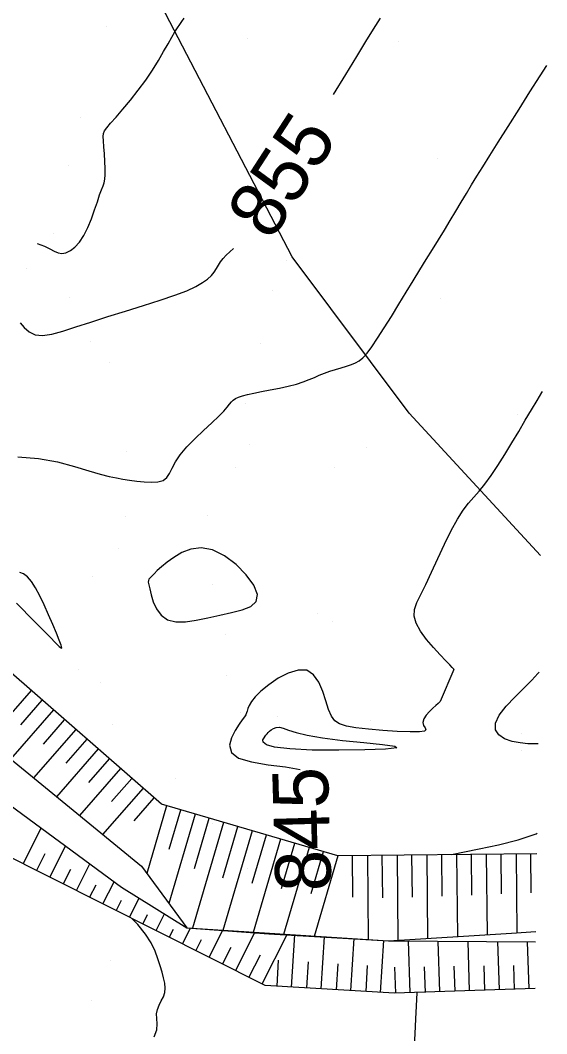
# Model space of a CAD drawing. Extents: x 400243 to 403697, y 4403637 to 4408083.
# Drawn here: x 403024.9 to 403095.7, y 4406214.4 to 4406350.8 of the extents above; entities that cross this region are included whole.
import ezdxf

# ---------------------------------------------------------------- set-up
doc = ezdxf.new("R2010")
doc.units = 0
doc.layers.add('HH_IC', color=7, linetype='Continuous')

msp = doc.modelspace()

# ---------------------------------------------------------------- linework, layer by layer
at = {"layer": 'HH_IC'}
for p, q in [((403061.46, 4406318.99), (403038.98, 4406362.21)), ((403036.51, 4406349.98), (403036.51, 4406349.98)), ((403055.41, 4406348.4), (403055.41, 4406348.4)), ((403075.73, 4406348.02), (403075.73, 4406348.02)), ((403032.92, 4406337.8), (403032.92, 4406337.8)), ((403031.33, 4406331.25), (403031.33, 4406331.25)), ((403081, 4406332.21), (403081, 4406332.21)), ((403060.68, 4406330.52), (403060.68, 4406330.52)), ((403029.3, 4406322.1), (403029.3, 4406322.1)), ((403061.46, 4406318.99), (403061.46, 4406318.99)), ((403077.2, 4406297.93), (403061.46, 4406318.99)), ((403060.74, 4406318.52), (403060.74, 4406318.52)), ((403025.73, 4406317.41), (403025.73, 4406317.41)), ((403031.47, 4406313.56), (403031.47, 4406313.56)), ((403058.75, 4406314.5), (403058.75, 4406314.5)), ((403081.37, 4406313.4), (403081.37, 4406313.4)), ((403034.38, 4406307.58), (403034.38, 4406307.58)), ((403057.14, 4406307.34), (403057.14, 4406307.34)), ((403036.88, 4406304.71), (403036.88, 4406304.71)), ((403055.11, 4406299.27), (403055.11, 4406299.27)), ((403077.2, 4406297.93), (403077.2, 4406297.93)), ((403094.88, 4406278.76), (403077.2, 4406297.93)), ((403091.72, 4406297.78), (403091.72, 4406297.78)), ((403055.73, 4406293.67), (403055.73, 4406293.67)), ((403071.52, 4406293.28), (403071.52, 4406293.28)), ((403039.17, 4406292.83), (403039.17, 4406292.83)), ((403053.79, 4406290.58), (403053.79, 4406290.58)), ((403067.09, 4406290.64), (403067.09, 4406290.64)), ((403039, 4406284.08), (403039, 4406284.08)), ((403050.03, 4406284.19), (403050.03, 4406284.19)), ((403038.04, 4406279.67), (403038.04, 4406279.67)), ((403034.58, 4406275.91), (403034.58, 4406275.91)), ((402983.55, 4406274.63), (403038.5, 4406234.11)), ((403050.69, 4406274.86), (403050.69, 4406274.86)), ((403064.8, 4406271.03), (403064.8, 4406271.03)), ((403066.88, 4406269.83), (403066.88, 4406269.83)), ((403052.55, 4406268.13), (403052.55, 4406268.13)), ((403043.88, 4406245.29), (403022.92, 4406263.59)), ((403032.76, 4406263.37), (403032.76, 4406263.37)), ((403035.68, 4406261.66), (403035.68, 4406261.66)), ((403052.57, 4406262.68), (403052.57, 4406262.68)), ((403026.32, 4406260.62), (403020.47, 4406253.91)), ((403024.92, 4406255.97), (403027.83, 4406259.3)), ((403029.33, 4406257.99), (403023.56, 4406251.38)), ((403054.53, 4406257.58), (403054.53, 4406257.58)), ((403027.97, 4406253.39), (403030.84, 4406256.67)), ((403059.46, 4406257.04), (403059.46, 4406257.04)), ((403071.95, 4406256.51), (403071.95, 4406256.51)), ((403032.35, 4406255.36), (403026.66, 4406248.84)), ((403037.32, 4406256.08), (403037.32, 4406256.08)), ((403092.37, 4406254.83), (403092.37, 4406254.83)), ((403019.57, 4406254.65), (403041.16, 4406236.95)), ((403031.03, 4406250.81), (403033.85, 4406254.04)), ((403035.36, 4406252.73), (403029.75, 4406246.3)), ((403059.55, 4406253.3), (403059.55, 4406253.3)), ((403092.3, 4406252.54), (403092.3, 4406252.54)), ((403034.08, 4406248.22), (403036.87, 4406251.41)), ((403038.37, 4406250.1), (403032.85, 4406243.76)), ((403037.14, 4406245.64), (403039.88, 4406248.78)), ((403045.72, 4406248.79), (403045.72, 4406248.79)), ((403041.39, 4406247.46), (403035.94, 4406241.23)), ((403040.19, 4406243.05), (403042.89, 4406246.15)), ((403043.88, 4406245.29), (403043.88, 4406245.29)), ((403067.61, 4406238.36), (403043.88, 4406245.29)), ((403044.54, 4406245.09), (403041.88, 4406235.97)), ((403048.38, 4406243.97), (403044.87, 4406231.93)), ((403044.92, 4406239.24), (403046.46, 4406244.53)), ((403052.22, 4406242.85), (403048.06, 4406228.59)), ((403048.33, 4406236.66), (403050.3, 4406243.41)), ((403050.69, 4406242.7), (403050.69, 4406242.7)), ((403025.27, 4406237.28), (403027.69, 4406242.08)), ((403052.12, 4406235.37), (403054.14, 4406242.29)), ((403056.06, 4406241.73), (403052.14, 4406228.3)), ((403056.08, 4406234.66), (403057.98, 4406241.17)), ((403057.81, 4406220.9), (403017.84, 4406241.02)), ((403059.9, 4406240.61), (403056.22, 4406228.01)), ((403060.04, 4406233.96), (403061.82, 4406240.05)), ((403088.41, 4406240.11), (403088.41, 4406240.11)), ((403028.19, 4406238.63), (403027.06, 4406236.38)), ((403028.84, 4406235.48), (403030.95, 4406239.67)), ((403063.74, 4406239.49), (403060.31, 4406227.74)), ((403064.01, 4406233.28), (403065.66, 4406238.93)), ((403067.58, 4406238.37), (403064.41, 4406227.5)), ((403094.37, 4406238.62), (403067.61, 4406238.36)), ((403067.61, 4406238.36), (403067.61, 4406238.36)), ((403069.63, 4406232.79), (403069.58, 4406238.38)), ((403071.58, 4406238.4), (403071.69, 4406227.07)), ((403073.64, 4406232.69), (403073.58, 4406238.42)), ((403075.58, 4406238.44), (403075.69, 4406226.99)), ((403077.63, 4406232.79), (403077.58, 4406238.46)), ((403079.58, 4406238.48), (403079.69, 4406227.23)), ((403081.63, 4406232.93), (403081.58, 4406238.5)), ((403083.58, 4406238.52), (403083.69, 4406227.48)), ((403085.63, 4406233.07), (403085.58, 4406238.54)), ((403087.58, 4406238.56), (403087.68, 4406227.73)), ((403089.63, 4406233.22), (403089.58, 4406238.58)), ((403091.58, 4406238.59), (403091.68, 4406227.98)), ((403093.63, 4406233.36), (403093.58, 4406238.61)), ((403032.42, 4406233.68), (403034.22, 4406237.26)), ((403031.61, 4406236.53), (403030.63, 4406234.58)), ((403041.16, 4406236.95), (403041.16, 4406236.95)), ((403041.16, 4406236.95), (403047.3, 4406228.64)), ((403055.49, 4406236.62), (403055.49, 4406236.62)), ((403035.03, 4406234.42), (403034.2, 4406232.79)), ((403035.99, 4406231.89), (403037.49, 4406234.86)), ((403038.5, 4406234.11), (403038.5, 4406234.11)), ((403038.5, 4406234.11), (403047.3, 4406228.64)), ((403038.46, 4406232.35), (403037.78, 4406230.99)), ((403039.56, 4406230.09), (403040.85, 4406232.65)), ((403041.95, 4406230.39), (403041.35, 4406229.19)), ((403043.14, 4406228.29), (403044.26, 4406230.53)), ((403045.45, 4406228.43), (403044.92, 4406227.39)), ((403046.71, 4406226.49), (403047.78, 4406228.61)), ((403047.3, 4406228.64), (403047.3, 4406228.64)), ((403047.3, 4406228.64), (403058.31, 4406227.86)), ((403047.3, 4406228.64), (403074.42, 4406226.91)), ((403050.28, 4406224.69), (403052.11, 4406228.33)), ((403053.86, 4406222.89), (403056.45, 4406228.06)), ((403057.43, 4406221.1), (403060.79, 4406227.78)), ((403058.31, 4406227.86), (403058.31, 4406227.86)), ((403058.31, 4406227.86), (403074.42, 4406226.91)), ((403061.38, 4406220.68), (403061.81, 4406227.71)), ((403065.37, 4406220.44), (403065.8, 4406227.46)), ((403074.42, 4406226.91), (403090.96, 4406227.94)), ((403090.96, 4406227.94), (403094.24, 4406228.15)), ((403090.96, 4406227.94), (403090.96, 4406227.94)), ((403049.22, 4406227.03), (403048.5, 4406225.59)), ((403069.36, 4406220.2), (403069.79, 4406227.2)), ((403073.35, 4406219.95), (403073.78, 4406226.95)), ((403074.42, 4406226.91), (403074.42, 4406226.91)), ((403074.42, 4406226.91), (403094.22, 4406226.76)), ((403077.35, 4406219.91), (403077.12, 4406226.89)), ((403081.35, 4406220.04), (403081.12, 4406226.86)), ((403085.34, 4406220.17), (403085.12, 4406226.83)), ((403089.34, 4406220.31), (403089.13, 4406226.8)), ((403093.34, 4406220.44), (403093.13, 4406226.77)), ((403053.18, 4406225.99), (403052.07, 4406223.79)), ((403057.13, 4406224.96), (403055.64, 4406222)), ((403037.07, 4406224.25), (403037.07, 4406224.25)), ((403059.59, 4406224.32), (403059.38, 4406220.81)), ((403063.59, 4406224.07), (403063.37, 4406220.56)), ((403067.58, 4406223.82), (403067.36, 4406220.32)), ((403071.57, 4406223.57), (403071.36, 4406220.07)), ((403075.23, 4406223.37), (403075.35, 4406219.84)), ((403079.23, 4406223.42), (403079.35, 4406219.97)), ((403083.23, 4406223.48), (403083.35, 4406220.11)), ((403087.23, 4406223.53), (403087.34, 4406220.24)), ((403091.23, 4406223.58), (403091.34, 4406220.37)), ((403057.81, 4406220.9), (403057.81, 4406220.9)), ((403075.22, 4406219.84), (403057.81, 4406220.9)), ((403094.14, 4406220.47), (403075.22, 4406219.84)), ((403075.22, 4406219.84), (403075.22, 4406219.84)), ((403034.43, 4406218.89), (403034.43, 4406218.89))]:
    msp.add_line(p, q, dxfattribs=at)
for points in [[(403027.14, 4406320.77), (403028.12, 4406320.41), (403028.86, 4406320.05), (403029.45, 4406319.74), (403029.95, 4406319.52), (403030.46, 4406319.44), (403031.01, 4406319.54), (403031.61, 4406319.82), (403032.23, 4406320.3), (403032.84, 4406320.97), (403033.43, 4406321.85), (403033.96, 4406322.92), (403034.45, 4406324.11), (403034.87, 4406325.3), (403035.24, 4406326.41), (403035.55, 4406327.34), (403035.81, 4406328.02), (403036.01, 4406328.53), (403036.15, 4406328.96), (403036.25, 4406329.43), (403036.29, 4406330.04), (403036.28, 4406330.87), (403036.24, 4406331.84), (403036.18, 4406332.85), (403036.11, 4406333.81), (403036.05, 4406334.6), (403036.01, 4406335.17), (403036.05, 4406335.58), (403036.19, 4406335.94), (403036.5, 4406336.36), (403037.01, 4406336.96), (403037.75, 4406337.8), (403038.67, 4406338.87), (403039.69, 4406340.09), (403040.74, 4406341.42), (403041.76, 4406342.78), (403042.66, 4406344.13), (403043.46, 4406345.42), (403044.16, 4406346.62), (403044.75, 4406347.68), (403045.25, 4406348.57), (403045.67, 4406349.27), (403046.02, 4406349.82), (403046.33, 4406350.26), (403046.63, 4406350.67), (403046.93, 4406351.1)], [(403067.01, 4406340.82), (403068.67, 4406343.53), (403070.16, 4406345.96), (403071.39, 4406347.96), (403072.41, 4406349.62), (403073.34, 4406351.13)], [(403024.52, 4406292.05), (403027.32, 4406291.85), (403029.89, 4406291.37), (403032.17, 4406290.77), (403034.1, 4406290.18), (403035.62, 4406289.74), (403036.81, 4406289.43), (403037.8, 4406289.22), (403038.68, 4406289.07), (403039.57, 4406288.94), (403040.53, 4406288.8), (403041.54, 4406288.68), (403042.52, 4406288.63), (403043.4, 4406288.69), (403044.11, 4406288.89), (403044.61, 4406289.27), (403044.97, 4406289.83), (403045.31, 4406290.54), (403045.75, 4406291.38), (403046.38, 4406292.35), (403047.28, 4406293.42), (403048.38, 4406294.53), (403049.54, 4406295.62), (403050.65, 4406296.64), (403051.59, 4406297.52), (403052.27, 4406298.21), (403052.73, 4406298.75), (403053.04, 4406299.15), (403053.28, 4406299.46), (403053.52, 4406299.7), (403053.82, 4406299.91), (403054.22, 4406300.09), (403054.75, 4406300.26), (403055.43, 4406300.44), (403056.29, 4406300.63), (403057.34, 4406300.84), (403058.51, 4406301.07), (403059.74, 4406301.32), (403060.94, 4406301.58), (403062.03, 4406301.86), (403062.95, 4406302.16), (403063.74, 4406302.46), (403064.44, 4406302.76), (403065.11, 4406303.05), (403065.79, 4406303.33), (403066.53, 4406303.59), (403067.29, 4406303.83), (403068.05, 4406304.06), (403068.77, 4406304.28), (403069.42, 4406304.49), (403069.98, 4406304.71), (403070.48, 4406304.99), (403070.98, 4406305.4), (403071.53, 4406306), (403072.17, 4406306.86), (403072.96, 4406308.02), (403073.85, 4406309.42), (403074.82, 4406310.97), (403075.81, 4406312.6), (403076.8, 4406314.22), (403077.74, 4406315.76), (403078.64, 4406317.22), (403079.51, 4406318.61), (403080.34, 4406319.96), (403081.15, 4406321.28), (403081.94, 4406322.59), (403082.71, 4406323.88), (403083.47, 4406325.13), (403084.2, 4406326.35), (403084.91, 4406327.53), (403085.6, 4406328.66), (403086.31, 4406329.83), (403087.11, 4406331.11), (403088.05, 4406332.61), (403089.18, 4406334.4), (403090.52, 4406336.53), (403091.99, 4406338.85), (403093.46, 4406341.19), (403094.83, 4406343.35), (403095.71, 4406344.74)], [(403024.85, 4406310.12), (403025.41, 4406309.47), (403026.06, 4406308.88), (403026.85, 4406308.49), (403027.86, 4406308.39), (403029.11, 4406308.58), (403030.6, 4406308.98), (403032.34, 4406309.55), (403034.36, 4406310.21), (403036.63, 4406310.94), (403039.04, 4406311.68), (403041.44, 4406312.42), (403043.71, 4406313.15), (403045.68, 4406313.82), (403047.27, 4406314.43), (403048.49, 4406314.99), (403049.41, 4406315.51), (403050.08, 4406316), (403050.58, 4406316.47), (403050.95, 4406316.93), (403051.26, 4406317.4), (403051.53, 4406317.86), (403051.81, 4406318.32), (403052.16, 4406318.77), (403052.59, 4406319.23), (403053.07, 4406319.67), (403053.57, 4406320.1)], [(403083.22, 4406263.45), (403083.21, 4406263.46), (403083.15, 4406263.53), (403082.99, 4406263.7), (403082.66, 4406264.04), (403082.13, 4406264.59), (403081.36, 4406265.4), (403080.46, 4406266.39), (403079.54, 4406267.49), (403078.72, 4406268.61), (403078.14, 4406269.66), (403077.89, 4406270.6), (403077.94, 4406271.49), (403078.25, 4406272.43), (403078.76, 4406273.52), (403079.44, 4406274.87), (403080.22, 4406276.53), (403081.08, 4406278.39), (403081.97, 4406280.31), (403082.85, 4406282.13), (403083.69, 4406283.69), (403084.46, 4406284.9), (403085.18, 4406285.84), (403085.89, 4406286.64), (403086.61, 4406287.44), (403087.38, 4406288.37), (403088.22, 4406289.53), (403089.12, 4406290.89), (403090.06, 4406292.38), (403091.01, 4406293.93), (403091.94, 4406295.49), (403092.83, 4406296.99), (403093.67, 4406298.38), (403094.42, 4406299.63), (403095.06, 4406300.7), (403095.16, 4406300.87)], [(403044.68, 4406270.13), (403045.78, 4406269.86), (403047.09, 4406269.86), (403048.55, 4406270.07), (403050.11, 4406270.4), (403051.72, 4406270.76), (403053.3, 4406271.09), (403054.73, 4406271.46), (403055.88, 4406271.93), (403056.6, 4406272.59), (403056.77, 4406273.53), (403056.29, 4406274.77), (403055.28, 4406276.17), (403053.91, 4406277.56), (403052.33, 4406278.74), (403050.72, 4406279.54), (403049.2, 4406279.81), (403047.83, 4406279.64), (403046.6, 4406279.17), (403045.52, 4406278.53), (403044.62, 4406277.86), (403043.89, 4406277.25), (403043.31, 4406276.75), (403042.87, 4406276.33), (403042.55, 4406276), (403042.33, 4406275.76), (403042.18, 4406275.59), (403042.1, 4406275.42), (403042.09, 4406275.2), (403042.15, 4406274.84), (403042.28, 4406274.29), (403042.47, 4406273.49), (403042.77, 4406272.55), (403043.21, 4406271.59), (403043.83, 4406270.74), (403044.68, 4406270.13)], [(403027.48, 4406273.37), (403026.9, 4406274.43), (403026.36, 4406275.28), (403025.82, 4406275.92), (403025.31, 4406276.33), (403024.79, 4406276.5)], [(403024.34, 4406272.38), (403025.1, 4406271.59), (403026.01, 4406270.67), (403027, 4406269.67), (403027.98, 4406268.68), (403028.88, 4406267.77), (403029.62, 4406267.04), (403030.12, 4406266.54), (403030.4, 4406266.31), (403030.47, 4406266.36), (403030.37, 4406266.7), (403030.11, 4406267.36), (403029.72, 4406268.32), (403029.23, 4406269.51), (403028.67, 4406270.81), (403028.07, 4406272.14), (403027.48, 4406273.37)], [(403081.39, 4406259.12), (403081.38, 4406259.11), (403081.35, 4406259.09), (403081.26, 4406259.01), (403081.09, 4406258.85), (403080.8, 4406258.6), (403080.39, 4406258.24), (403079.93, 4406257.79), (403079.49, 4406257.29), (403079.17, 4406256.79), (403079.04, 4406256.31), (403079.15, 4406255.9), (403079.36, 4406255.57), (403079.46, 4406255.31), (403079.27, 4406255.13), (403078.6, 4406255.03), (403077.32, 4406255.03), (403075.6, 4406255.09), (403073.66, 4406255.21), (403071.73, 4406255.38), (403070.03, 4406255.58), (403068.75, 4406255.8), (403067.83, 4406256.1), (403067.19, 4406256.54), (403066.73, 4406257.17), (403066.36, 4406258.05), (403065.99, 4406259.2), (403065.57, 4406260.49), (403065.03, 4406261.73), (403064.33, 4406262.73), (403063.41, 4406263.32), (403062.25, 4406263.36), (403060.93, 4406262.96), (403059.58, 4406262.25), (403058.32, 4406261.39), (403057.26, 4406260.51), (403056.49, 4406259.75), (403055.98, 4406259.11), (403055.68, 4406258.58), (403055.5, 4406258.16), (403055.4, 4406257.84), (403055.31, 4406257.59), (403055.2, 4406257.35), (403055.02, 4406257.07), (403054.74, 4406256.66), (403054.32, 4406256.06), (403053.77, 4406255.23), (403053.27, 4406254.25), (403053.03, 4406253.23), (403053.27, 4406252.28), (403054.22, 4406251.5), (403055.98, 4406250.98), (403058.24, 4406250.62), (403060.56, 4406250.32), (403062.52, 4406249.95)], [(403083.22, 4406263.45), (403081.39, 4406259.12)], [(403092.12, 4406253.54), (403091.04, 4406253.76), (403090.05, 4406254.12), (403089.26, 4406254.63), (403088.8, 4406255.32), (403088.8, 4406256.2), (403089.32, 4406257.28), (403090.25, 4406258.48), (403091.41, 4406259.72), (403092.61, 4406260.92), (403093.69, 4406261.99), (403094.5, 4406262.88), (403094.68, 4406263.09)], [(403059.74, 4406255.65), (403060.25, 4406255.52), (403060.96, 4406255.28), (403061.99, 4406254.95), (403063.48, 4406254.59), (403065.55, 4406254.23), (403068.23, 4406253.89), (403071.1, 4406253.59), (403073.62, 4406253.32), (403075.27, 4406253.09), (403075.52, 4406252.88), (403074.03, 4406252.72), (403071.23, 4406252.61), (403067.74, 4406252.56), (403064.16, 4406252.59), (403061.12, 4406252.73), (403059.1, 4406252.97), (403057.99, 4406253.29), (403057.54, 4406253.64), (403057.52, 4406253.97), (403057.68, 4406254.25), (403057.82, 4406254.45), (403057.91, 4406254.59), (403057.99, 4406254.69), (403058.08, 4406254.79), (403058.21, 4406254.93), (403058.39, 4406255.12), (403058.63, 4406255.33), (403058.94, 4406255.51), (403059.31, 4406255.63), (403059.74, 4406255.65)], [(403094.56, 4406253.43), (403094.12, 4406253.41), (403093.15, 4406253.43), (403092.12, 4406253.54)], [(403082.91, 4406238.51), (403086.63, 4406239.31), (403089.24, 4406239.82), (403091.88, 4406240.48), (403094.28, 4406241.33), (403094.41, 4406241.39)], [(403042.9, 4406213.98), (403043.23, 4406214.91), (403043.29, 4406215.72), (403043.23, 4406216.43), (403043.2, 4406217.08), (403043.32, 4406217.68), (403043.56, 4406218.25), (403043.84, 4406218.81), (403044.12, 4406219.36), (403044.31, 4406219.94), (403044.37, 4406220.55), (403044.31, 4406221.2), (403044.16, 4406221.91), (403043.95, 4406222.68), (403043.69, 4406223.54), (403043.39, 4406224.48), (403043.02, 4406225.51), (403042.49, 4406226.62), (403041.74, 4406227.82), (403040.7, 4406229.1), (403039.84, 4406229.95)], [(403078.24, 4406219.94), (403078.16, 4406218.13), (403078.07, 4406216.42), (403077.95, 4406214.4), (403077.81, 4406212.2)]]:
    msp.add_lwpolyline(points, dxfattribs=at)

# ---------------------------------------------------------------- texts
for s, rotation, p in [('855', 57.029, (403058.59, 4406320.95)), ('845', 91.6278, (403066.73, 4406233.65))]:
    msp.add_text(s, height=7.5, rotation=rotation, dxfattribs=at).set_placement(p)

doc.saveas('drawing.dxf')
